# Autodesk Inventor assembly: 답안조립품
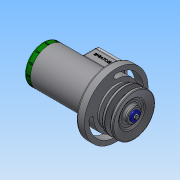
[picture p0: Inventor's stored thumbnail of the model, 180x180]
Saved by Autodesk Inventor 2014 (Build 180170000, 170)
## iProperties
Created: 2017-05
Part Number: 답안조립품
Document SubType Name: Assembly
Designer: NET
Author: NET
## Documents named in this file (20)
- C:\Users\NET\Desktop\470507V1016\답안조립품.iam
- C:\Users\NET\Desktop\470507V1016\답안부품.ipt
- C:\Users\NET\Desktop\470507V1016\축.ipt
- C:\Users\NET\Desktop\470507V1016\키 4 x 4 x 18.ipt
- C:\Users\NET\Desktop\470507V1016\V-벨트풀리.ipt
- C:\Users\NET\Desktop\470507V1016\볼트 M4 x 10.ipt
- C:\Users\NET\Desktop\470507V1016\와셔 4x16.ipt
- C:\Users\NET\Desktop\470507V1016\사이드 커버.ipt
- 사이드 커버.ipt
- C:\Users\NET\Desktop\470507V1016\너트 M10.ipt
- C:\Users\NET\Desktop\470507V1016\와셔 10x21.ipt
- C:\Users\NET\Desktop\470507V1016\멈춤링 35x1.6.ipt
- C:\Users\NET\Desktop\470507V1016\부시1.ipt
- C:\Users\NET\Desktop\470507V1016\베어링 15 x 35 x 11.ipt
- C:\Users\NET\Desktop\470507V1016\부시2.ipt
- C:\Users\NET\Desktop\470507V1016\멈춤링 15 x 1.ipt
- C:\Users\NET\Desktop\470507V1016\탑 커버.ipt
- C:\Users\NET\Desktop\470507V1016\와셔 3x6.ipt
- C:\Users\NET\Desktop\470507V1016\십자볼트 M3 x 10.ipt
- C:\Users\NET\Desktop\470507V1016\오일 실 15 25 7.ipt
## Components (2 placed, 2 different names)
1. V-벨트풀리:1
2. ISO 4017 M4 x 10:1
